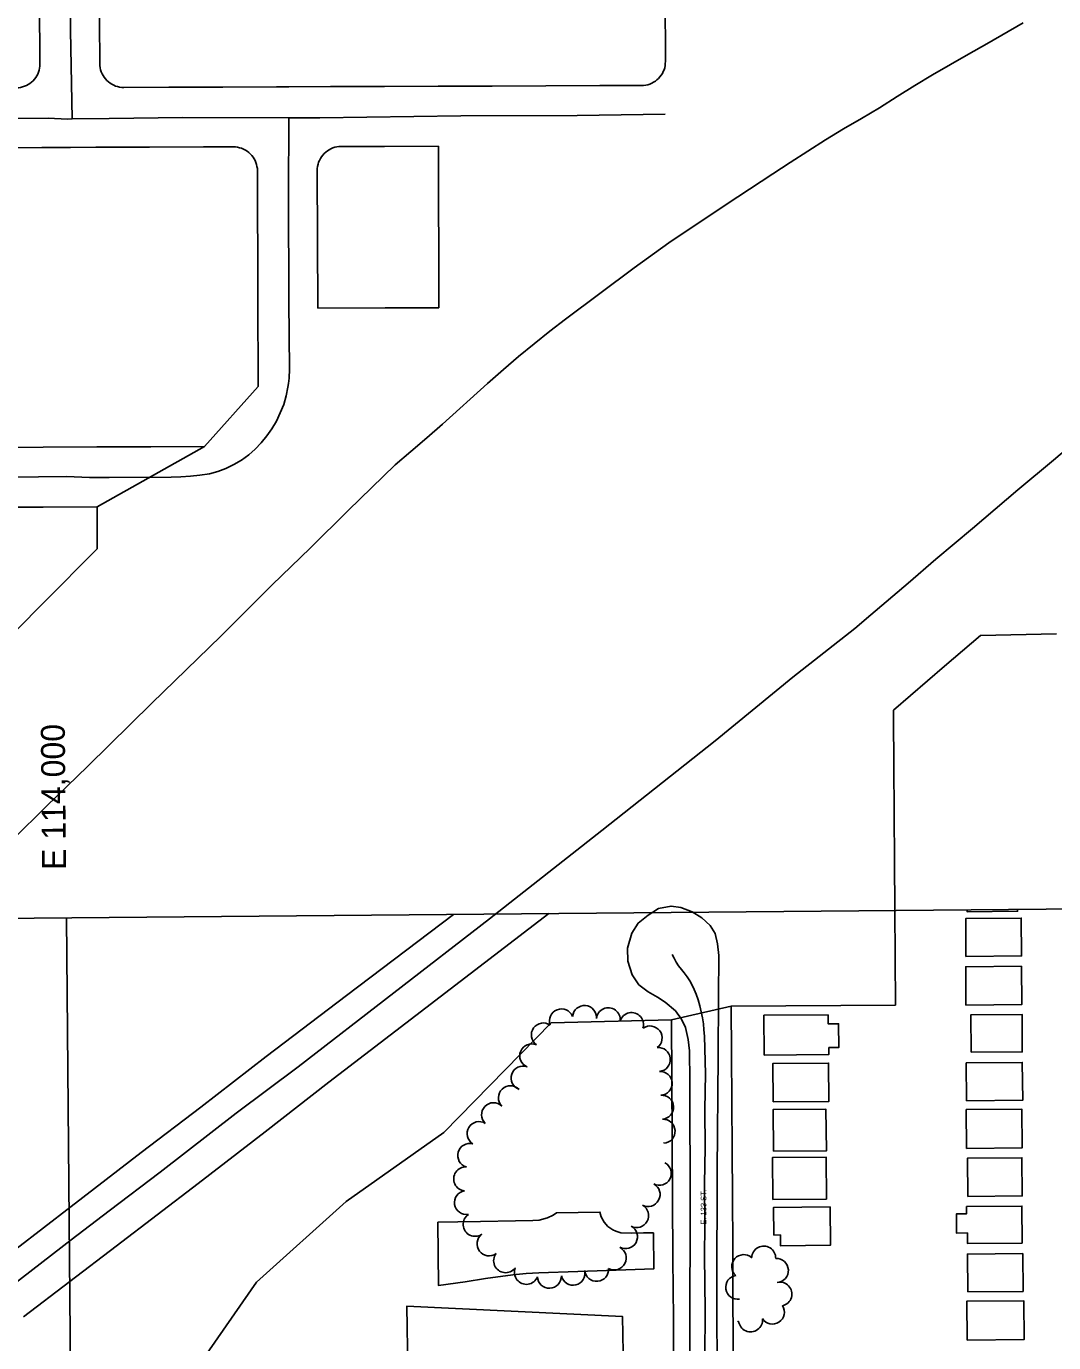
# Model space of a CAD drawing. Extents: x -2233 to 187241, y 4582 to 150524.
# Drawn here: x 113957 to 114816, y 59724 to 60823 of the extents above; entities that cross this region are included whole.
import ezdxf

# ---------------------------------------------------------------- set-up
doc = ezdxf.new("R2010")
doc.units = 0
for name, color, linetype in [('60', 7, 'Continuous'), ('AP_X_Misc', 7, 'Continuous'), ('BLDG', 7, 'Continuous'), ('GE_X_CL_2000', 7, 'Continuous'), ('GRID', 7, 'Continuous'), ('INTERSTATE', 7, 'Continuous'), ('ROAD', 7, 'Continuous'), ('ROAD-NAME', 7, 'Continuous'), ('RW_X_Fee_RW', 7, 'Continuous'), ('TREES', 7, 'Continuous')]:
    doc.layers.add(name, color=color, linetype=linetype)

msp = doc.modelspace()

# ---------------------------------------------------------------- linework, layer by layer
at = {"layer": '60'}
msp.add_line((109991.1, 60043.6), (114990.9, 60087.2), dxfattribs=at)
at = {"layer": 'AP_X_Misc'}
for points in [[(114301.1, 59824.2), (114301.8, 59771.2), (114324, 59774.5), (114341.1, 59777.2), (114363.8, 59780.3), (114375, 59781.3), (114385.6, 59781.8), (114418.1, 59783), (114458.3, 59784.4), (114481.7, 59785.3), (114481.2, 59815.3), (114472.9, 59815.2), (114462.7, 59815), (114454.1, 59815.3), (114449.8, 59816.6), (114447.3, 59817.8), (114443.3, 59820.7), (114440.2, 59824.1), (114437.7, 59828.8), (114436.6, 59832.6), (114400.3, 59832.1), (114397.5, 59830.1), (114392.8, 59827.8), (114385.8, 59825.9), (114380.4, 59825.6), (114366, 59825.4), (114336.8, 59824.8), (114318, 59824.5)], [(114276.1, 59701.2), (114455.9, 59715.3), (114455.5, 59745.3), (114275.3, 59754.2)]]:
    msp.add_lwpolyline(points, close=True, dxfattribs=at)
at = {"layer": 'BLDG'}
for points in [[(114742.3, 60046.2), (114788.8, 60046.6), (114788.5, 60078.2), (114742.1, 60077.8)], [(114742.3, 60005.5), (114788.9, 60005.9), (114788.7, 60038), (114742.1, 60037.6)], [(114627.8, 59970), (114636.1, 59970), (114635.9, 59990), (114627.1, 59989.9), (114627.1, 59997.4), (114573.5, 59997), (114573.8, 59963.8), (114627.8, 59964.3)], [(114746.6, 59966.1), (114789.4, 59966.4), (114789.2, 59997.8), (114746.3, 59997.4)], [(114581.2, 59924.6), (114627.9, 59925.1), (114627.6, 59957.1), (114580.9, 59956.7)], [(114742.7, 59925.7), (114789.7, 59926.1), (114789.4, 59957.7), (114742.5, 59957.2)], [(114581.5, 59883.4), (114625.7, 59883.8), (114625.4, 59918.6), (114581.2, 59918.2)], [(114742.8, 59885.8), (114789.2, 59886.2), (114788.9, 59918.7), (114742.5, 59918.3)], [(114580.9, 59843.1), (114625.8, 59843.5), (114625.5, 59878.6), (114580.6, 59878.2)], [(114743.8, 59845.8), (114789.3, 59846.2), (114789.1, 59878), (114743.6, 59877.6)], [(114581.8, 59813.5), (114587.3, 59813.6), (114587.4, 59804.5), (114629.1, 59804.9), (114628.8, 59837), (114581.6, 59836.6)], [(114789.4, 59806.7), (114743.7, 59806.3), (114743.6, 59815.2), (114734.4, 59815.1), (114734.3, 59831.1), (114742.8, 59831.2), (114742.8, 59837.2), (114789.1, 59837.6)], [(114743.9, 59766), (114790, 59766.4), (114789.7, 59798), (114743.6, 59797.6)], [(114743.3, 59725.8), (114790.9, 59726.2), (114790.6, 59758.6), (114743, 59758.2)]]:
    msp.add_lwpolyline(points, close=True, dxfattribs=at)
msp.add_lwpolyline([(114743.3, 60085.1), (114743.3, 60083.5), (114785.4, 60083.9), (114785.3, 60085.4)], dxfattribs=at)
at = {"layer": 'GE_X_CL_2000'}
for points in [[(113988.8, 61490.7), (113988.8, 61468.7), (113989.4, 61446.5), (113990, 61402.4), (113990.2, 61354.9), (113990.2, 61317.2), (113991, 61255.4), (113990.8, 61210.1), (113991.2, 61164), (113991.8, 61105.2), (113992.5, 61063.3), (113992.6, 61009.2), (113992.7, 60972.8), (113993.4, 60931.3), (113993.5, 60896), (113994, 60859.9), (113994.3, 60819.7), (113995.6, 60745.7)], [(114790.2, 60825.9), (114759.7, 60808.4), (114744.5, 60799.9), (114729.4, 60791.3), (114714.4, 60782.5), (114699.5, 60773.5), (114684.8, 60764.4), (114670.1, 60755), (114655, 60746.2), (114640, 60737.3), (114625, 60728.2), (114610.2, 60718.9), (114595.5, 60709.4), (114580.9, 60699.8), (114551.8, 60680.7), (114522.9, 60661.5), (114494, 60642.2), (114465.1, 60621.2), (114436.4, 60600), (114407.8, 60578.5), (114394.6, 60568.3), (114381.5, 60557.9), (114368.6, 60547.2), (114355.9, 60536.4), (114342.6, 60524.8), (114305.1, 60490.8), (114292, 60479.3), (114278.7, 60468), (114265.4, 60456.9), (114226.3, 60418.7), (114194.4, 60387.3), (114162.7, 60356.7), (114137.7, 60331.5), (114119.9, 60313.7), (114062.3, 60257.6), (114026.6, 60222.6), (114008.7, 60205), (113973.9, 60171.5), (113918.6, 60116.8)], [(113945.8, 60746.2), (113975.7, 60746.4), (113991.9, 60745.6), (113995.6, 60745.7)], [(113995.6, 60745.7), (114026.6, 60746.1), (114088.2, 60746.9), (114176.8, 60746.6)], [(114153.7, 60475.3), (114158.2, 60481), (114162.5, 60487), (114166.3, 60493.4), (114169.6, 60500.2), (114172.4, 60507.2), (114174.5, 60514.4), (114176, 60521.8), (114176.4, 60524.8), (114176.9, 60529.2), (114177.2, 60536.6), (114176.7, 60593.1), (114176.3, 60682.6), (114176.8, 60746.6)], [(114176.8, 60746.6), (114202.6, 60746.5), (114320.5, 60748.2), (114417.5, 60748.5), (114491, 60749.6)], [(113937.1, 59764.6), (113994.8, 59809.5), (114026.6, 59833.7), (114069.3, 59866.1), (114132.7, 59915.2), (114184.6, 59954), (114344.2, 60077.5), (114438.2, 60151.3), (114532.8, 60226.2), (114597.8, 60279.4), (114649.5, 60320.1), (114662.9, 60331.5), (114694, 60357.9), (114717.1, 60378), (114747.9, 60403.5), (114785.6, 60435.9), (114815.3, 60460.8), (114847.2, 60487.8)], [(113677.8, 60444.6), (113706.1, 60445.6), (113747.9, 60445.3), (113835.8, 60445.4), (113888.2, 60446.1), (113944.1, 60446.6), (113991, 60447), (114010.2, 60446.1), (114026.6, 60446.2), (114078.5, 60446.5), (114086.5, 60446.8), (114094.5, 60447.3), (114102.5, 60448.1), (114110.4, 60449.2), (114117.4, 60451.1), (114124.2, 60453.7), (114130.9, 60457), (114137.2, 60460.8), (114143.2, 60465.2), (114148.7, 60470), (114153.7, 60475.3)], [(114496.9, 60047.9), (114498.5, 60044.6), (114500.3, 60041.3), (114502.3, 60038.2), (114504.6, 60035.3), (114507, 60032.5), (114509.4, 60029.2), (114511.6, 60025.7), (114513.6, 60022.2), (114515.4, 60018.5), (114517, 60014.7), (114518.6, 60009.8), (114520, 60004.9), (114521.2, 59999.9), (114522.2, 59994.9), (114523, 59989.9), (114523.5, 59984.8), (114523.9, 59979.7), (114524.7, 59948), (114524.3, 59918.2), (114524.4, 59886.2), (114524, 59856.6), (114524.1, 59822.1), (114523.9, 59795.7), (114524.4, 59750.4), (114524.1, 59710.9)]]:
    msp.add_lwpolyline(points, dxfattribs=at)
at = {"layer": 'GRID'}
for p, q in [((114990.9, 60087.2), (109991.1, 60043.6)), ((113990.9, 60078.5), (114014.5, 57380.8))]:
    msp.add_line(p, q, dxfattribs=at)
at = {"layer": 'INTERSTATE'}
for points in [[(114314.3, 60081.3), (114225, 60013.6), (114157.9, 59962.7), (114103.1, 59920.2), (114053.5, 59882.3), (113994.9, 59837.4), (113925.3, 59783.9)], [(113955.2, 59745.1), (114032.4, 59804.1), (114101, 59856.6), (114156.9, 59899.7), (114210.1, 59941.1), (114274.5, 59990.4), (114394, 60082)]]:
    msp.add_lwpolyline(points, dxfattribs=at)
at = {"layer": 'ROAD'}
msp.add_lwpolyline([(114534.4, 59685.4), (114534.2, 59768.2), (114534.6, 59867.1), (114535.4, 59963), (114535.6, 60012.4), (114535.8, 60047.1), (114534.8, 60056.6), (114532.7, 60065.3), (114528.6, 60072), (114521.7, 60078.3), (114513.7, 60083.5), (114504.2, 60087.1), (114496, 60088.2), (114485.4, 60086.2), (114476.9, 60080.7), (114468.6, 60074.1), (114463.3, 60065.6), (114459.7, 60053.2), (114460, 60042.1), (114463.6, 60030.9), (114469, 60022.5), (114476.9, 60016.5), (114484.7, 60012.2), (114491.1, 60008.1), (114499.8, 60000.7), (114504.8, 59993.8), (114508.1, 59986.9), (114510.4, 59976.9), (114511.4, 59967.2), (114511.7, 59942.2), (114511.9, 59835), (114511.7, 59737.8), (114512.3, 59645.4)], dxfattribs=at)
at = {"layer": 'RW_X_Fee_RW'}
for p, q in [((114491.3, 60793.7), (114490.6, 60908.9)), ((114302.1, 60588), (114301.7, 60723)), ((114150.5, 60702.4), (114150.9, 60597.3)), ((114200.5, 60702.6), (114200.9, 60587.6)), ((114150.9, 60597.3), (114151.2, 60522.2)), ((114106.4, 60472), (114151.2, 60522.2)), ((114106.4, 60472), (114016.5, 60421.7)), ((114016.5, 60421.7), (114016.7, 60386.7)), ((114754.5, 60314.2), (114817.9, 60315.5)), ((114496.3, 59993.1), (114546.3, 60004.7)), ((114683.5, 60005.6), (114546.3, 60004.7))]:
    msp.add_line(p, q, dxfattribs=at)
for points in [[(113968.8, 60791.6), (113968.1, 60896.3), (113967.8, 60945.1), (113967.6, 60990.1), (113967.3, 61035.1), (113967, 61080.1), (113966.7, 61125.1), (113966.4, 61170.1), (113966.1, 61215.1), (113965.9, 61260.1), (113965.6, 61305.5), (113964.7, 61446)], [(114018.8, 60791.9), (114018.1, 60897.5), (114017.8, 60945.4), (114017.6, 60990.4), (114017.3, 61035.4), (114017, 61080.4), (114016.7, 61125.4), (114016.4, 61170.4), (114016.1, 61215.4), (114015.9, 61260.4), (114015.6, 61305.8), (114014.7, 61444.3)], [(113949.1, 60771.7), (113950.8, 60771.8), (113952.5, 60772), (113954.2, 60772.4), (113955.9, 60773), (113957.5, 60773.6), (113959, 60774.4), (113960.4, 60775.4), (113961.8, 60776.4), (113963.1, 60777.6), (113964.2, 60778.9), (113965.3, 60780.2), (113966.2, 60781.7), (113967, 60783.2), (113967.6, 60784.8), (113968.1, 60786.5), (113968.5, 60788.2), (113968.7, 60789.9), (113968.8, 60791.6)], [(114018.8, 60791.9), (114018.9, 60790.2), (114019.1, 60788.5), (114019.5, 60786.8), (114020, 60785.1), (114020.7, 60783.5), (114021.5, 60782), (114022.5, 60780.5), (114023.5, 60779.1), (114024.7, 60777.8), (114026, 60776.7), (114027.4, 60775.6), (114028.9, 60774.7), (114030.4, 60773.9), (114032, 60773.2), (114033.7, 60772.7), (114035.4, 60772.3), (114037.1, 60772.1), (114038.9, 60772.1)], [(114471.4, 60773.6), (114473.1, 60773.7), (114474.9, 60773.9), (114476.6, 60774.3), (114478.2, 60774.8), (114479.8, 60775.5), (114481.4, 60776.3), (114482.9, 60777.3), (114484.2, 60778.3), (114485.5, 60779.5), (114486.7, 60780.8), (114487.7, 60782.2), (114488.7, 60783.7), (114489.5, 60785.2), (114490.1, 60786.8), (114490.7, 60788.5), (114491, 60790.2), (114491.2, 60792), (114491.3, 60793.7)], [(114038.9, 60772.1), (114076.5, 60772.2), (114121.5, 60772.3), (114166.5, 60772.5), (114176.8, 60772.5)], [(114176.8, 60772.5), (114211.5, 60772.7), (114256.5, 60772.8), (114301.5, 60773), (114346.5, 60773.1), (114391.5, 60773.3), (114436.5, 60773.5), (114471.4, 60773.6)], [(113800.4, 60721.2), (113835.4, 60721.3), (113880.4, 60721.5), (113925.4, 60721.6), (113970.4, 60721.8), (113994.2, 60721.9)], [(113994.2, 60721.9), (114015.4, 60722), (114060.4, 60722.1), (114105.4, 60722.3), (114130.4, 60722.4)], [(114150.5, 60702.4), (114150.4, 60704.2), (114150.1, 60705.9), (114149.8, 60707.6), (114149.2, 60709.3), (114148.6, 60710.9), (114147.7, 60712.4), (114146.8, 60713.9), (114145.7, 60715.3), (114144.5, 60716.6), (114143.3, 60717.7), (114141.9, 60718.8), (114140.4, 60719.7), (114138.8, 60720.5), (114137.2, 60721.2), (114135.6, 60721.7), (114133.9, 60722.1), (114132.1, 60722.3), (114130.4, 60722.4)], [(114220.4, 60722.7), (114218.6, 60722.6), (114216.9, 60722.4), (114215.2, 60722), (114213.6, 60721.5), (114211.9, 60720.8), (114210.4, 60720), (114208.9, 60719), (114207.5, 60718), (114206.3, 60716.8), (114205.1, 60715.5), (114204, 60714.1), (114203.1, 60712.6), (114202.3, 60711.1), (114201.6, 60709.5), (114201.1, 60707.8), (114200.7, 60706.1), (114200.5, 60704.4), (114200.5, 60702.6)], [(114220.4, 60722.7), (114256.7, 60722.8), (114301.7, 60723)], [(114200.9, 60587.6), (114257.1, 60587.8), (114302.1, 60588)], [(113721.4, 60470.7), (113746.4, 60470.8), (113791.4, 60470.9), (113836.4, 60471.1), (113881.4, 60471.2), (113926.4, 60471.4), (113971.4, 60471.5), (114016.4, 60471.7), (114061.4, 60471.9), (114106.4, 60472)], [(113721.5, 60420.7), (113746.5, 60420.8), (113791.5, 60420.9), (113836.5, 60421.1), (113881.5, 60421.2), (113926.5, 60421.4), (113971.5, 60421.5), (114016.5, 60421.7)], [(113927, 60296.4), (113971.8, 60341.5), (114016.7, 60386.7)], [(114681.9, 60252), (114724.5, 60288.5), (114754.5, 60314.2)], [(114681.9, 60252), (114681.9, 60245.6), (114682.2, 60205.6), (114682.4, 60165.6), (114682.7, 60125.6), (114683, 60085.6), (114683.2, 60045.6), (114683.5, 60005.6)], [(114548.8, 59590.3), (114548, 59724.7), (114547.7, 59764.7), (114547.5, 59804.7), (114547.2, 59844.7), (114547, 59884.7), (114546.8, 59924.7), (114546.5, 59964.7), (114546.3, 60004.7)], [(114496.3, 59993.1), (114395.9, 59990.6), (114306.2, 59899.2), (114224.5, 59841.4), (114149.7, 59774.1), (114089.6, 59687.6), (114157.4, 59640.5), (114157.7, 59591.4), (114408.8, 59595.2), (114448.8, 59595.8), (114479.3, 59596.1), (114498.8, 59616)], [(114496.3, 59993.2), (114497.6, 59793.5), (114497.9, 59743.5), (114498.7, 59616.2)]]:
    msp.add_lwpolyline(points, dxfattribs=at)
at = {"layer": 'TREES'}
for centre, radius, start, end in [((114404.4, 59992.4), 10, 21.4397, 201.4397), ((114423.7, 59995.2), 10, 355.2322, 175.2322), ((114443.6, 59993.3), 10, 354.1174, 174.1174), ((114463, 59989.3), 10, 342.1517, 162.1517), ((114389.3, 59980.6), 10, 54.3851, 234.3851), ((114478.5, 59978.1), 10, 306.2055, 126.2055), ((114379.6, 59963.2), 10, 67.1602, 247.1602), ((114485.4, 59960.1), 10, 275.6162, 95.6162), ((114372.3, 59944.6), 10, 70.3965, 250.3965), ((114486.9, 59940.2), 10, 273.4494, 93.4494), ((114361.8, 59928.2), 10, 43.9822, 223.9822), ((114347.7, 59914), 10, 46.4864, 226.4864), ((114488.1, 59920.2), 10, 273.4494, 93.4494), ((114335.6, 59898.2), 10, 58.8888, 238.8888), ((114489.3, 59900.2), 10, 273.4494, 93.4494), ((114327.8, 59880), 10, 74.7777, 254.7777), ((114489.9, 59890.3), 0.00000000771, 273.4204, 93.4204), ((114324.4, 59860.4), 10, 85.2518, 265.2518), ((114486.2, 59865), 10, 241.8455, 61.8455), ((114476.8, 59847.3), 10, 241.8455, 61.8455), ((114325.1, 59840.6), 10, 99.0306, 279.0306), ((114467.3, 59829.7), 10, 241.8455, 61.8455), ((114332.3, 59822.4), 10, 124.1268, 304.1268), ((114343.9, 59806.1), 10, 126.8294, 306.8294), ((114457.9, 59812.1), 10, 241.8455, 61.8455), ((114448.5, 59794.4), 10, 241.8455, 61.8455), ((114573.4, 59794.3), 10, 358.1283, 178.1283), ((114357.8, 59792), 10, 142.5278, 322.5278), ((114556.7, 59787.1), 10, 48.0137, 228.0137), ((114584, 59783.9), 10, 273.3812, 93.3812), ((114375.1, 59782.3), 10, 158.31, 338.31), ((114394.4, 59779), 10, 182.2783, 2.2783), ((114414.1, 59781.6), 10, 193.1968, 13.1968), ((114433.8, 59784.8), 10, 184.8349, 4.8349), ((114551.6, 59769.8), 10, 98.7242, 278.7242), ((114586.9, 59764.2), 10, 283.0832, 103.0832), ((114580.7, 59749.1), 10, 212.8222, 32.8222), ((114552.1, 59741.6), 0.337, 185.5584, 5.5584), ((114562.4, 59742.6), 10, 185.8689, 5.8689)]:
    msp.add_arc(centre, radius, start, end, dxfattribs=at)

# ---------------------------------------------------------------- texts
at = {"layer": 'GRID'}
msp.add_text('E 114,000', height=20, rotation=90.5, dxfattribs=at).set_placement((113990.6, 60118.5))
at = {"layer": 'ROAD-NAME'}
msp.add_text('E. 133 ST.', height=4.68, rotation=89.9987, dxfattribs=at).set_placement((114525.5, 59822.2))

doc.saveas('drawing.dxf')
